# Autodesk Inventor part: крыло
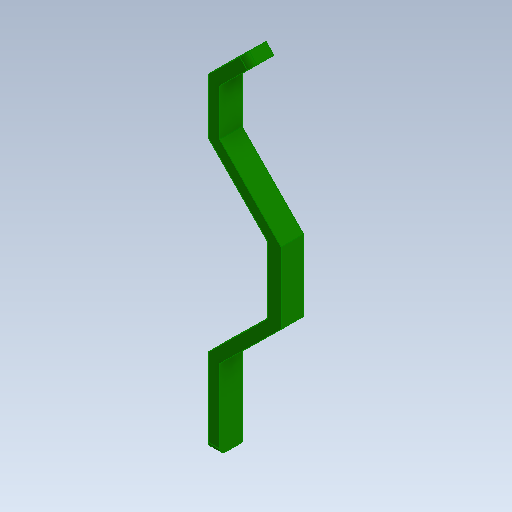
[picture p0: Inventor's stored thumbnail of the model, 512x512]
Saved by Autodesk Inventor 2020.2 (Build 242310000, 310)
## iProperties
Created: 2020-04
Part Number: крыло
Material: Типовые
Document SubType Name: Modeling
Designer: Алексей
Density: 1 g/cm^3
Appearance: По умолчанию
Author: Алексей
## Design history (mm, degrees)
sketch "Эскиз1"
  geometry: L1 (11, -78)-(4.414, -78) reference; L2 (11, -78)-(11, -74) reference; L3 (11, -74)-(25, -74) reference; L4 (25, -74)-(25, -78) reference; L5 (35, -78)-(25, -78) reference; L6 (35, -58)-(35, -78) reference; L7 (28.375, -58)-(35, -58) reference; L8 (35, -18)-(28.375, -18) reference; L9 (35, -2)-(35, -18) reference; L10 (35, -2)-(31, -2) reference; L11 (31, -2)-(31, 12) reference; L12 (31, 12)-(35, 12) reference; L13 (35, 28)-(35, 12) reference; L14 (28.375, 28)-(35, 28) reference; L15 (35, 68)-(28.375, 68) reference; L16 (35, 78)-(35, 68) reference; L17 (22, 78)-(35, 78) reference; L18 (22, 78)-(22, 74) reference; L19 (22, 74)-(8, 74) reference; L20 (8, 74)-(8, 78) reference; L21 (-5, 78)-(8, 78) reference; L22 (-7.718, 70.105)-(-5, 78) reference; L23 (-12.5, 67)-(-7.718, 70.105) reference; L24 (-13.093, 60.719)-(-12.5, 67) reference; L25 (-13.093, 60.719)-(-9.11, 60.343) reference; L26 (-9.11, 60.343)-(-10.425, 46.405) reference; L27 (-10.425, 46.405)-(-14.407, 46.781) reference; L28 (-15, 40.5)-(-14.407, 46.781) reference; L29 (-4.88, 34.8)-(-15, 40.5) reference; L30 (-2.58, 25.5)-(-4.88, 34.8) reference; L31 (-15.736, -18.735)-(-8.938, -18.9) reference; L32 (-34.328, -10.306)-(-15.736, -18.735) reference; L33 (-35, -16.306)-(-34.328, -10.306) reference; L34 (-26.476, -21.507)-(-35, -16.306) reference; L35 (-26.476, -21.507)-(-24.392, -18.092) reference; L36 (-24.392, -18.092)-(-12.441, -25.384) reference; L37 (-12.441, -25.384)-(-14.524, -28.799) reference; L38 (-6, -34)-(-14.524, -28.799) reference; L39 (-3.6, -49.087)-(-6, -34) reference; L40 (-3.6, -49.087)-(0.351, -48.458) reference; L41 (0.351, -48.458)-(2.55, -62.285) reference; L42 (2.55, -62.285)-(-1.4, -62.913) reference; L43 (0.464, -74.628)-(-1.4, -62.913) reference; L44 (8.375, -58)-(8.375, -29.617); L45 (8.375, -29.617)-(30.337, -8.02); L46 (30.337, -8.02)-(30.337, 17.48); L47 (30.337, 17.48)-(8.375, 39.814); L48 (8.375, 39.814)-(8.375, 56.383); L49 (8.375, 56.383)-(19.747, 67.565); L50 (19.747, 67.565)-(16.942, 70.417); L51 (16.942, 70.417)-(4.375, 58.059); L52 (4.375, 58.059)-(4.375, 38.177); L53 (4.375, 38.177)-(25.343, 16.854); L54 (25.343, 16.854)-(25.343, -7.321); L55 (25.343, -7.321)-(4.375, -27.941); L56 (4.375, -27.941)-(4.375, -58); L57 (4.375, -58)-(8.375, -58); L58 (-2.58, 25.5)-(15.848, 15.1) reference; L59 (15.848, 15.1)-(20.343, 10.529) reference; L60 (20.343, 10.529)-(20.343, -5.226) reference; L61 (20.343, -5.226)-(6.438, -18.9) reference; L62 (6.438, -18.9)-(-8.938, -18.9) reference; A1 r 4 centre (4.414, -74) between (0.464, -74.628) and (4.414, -78) reference; A2 r 20 centre (28.375, -38) between (28.375, -18) and (28.375, -58) reference; A3 r 20 centre (28.375, 48) between (28.375, 68) and (28.375, 28) reference; 1 further point
  constraints: 28 end point, 7 perpendicular, 5 tangent, 4 parallel, 2 point on line, 1 collinear, 1 vertical
  dimensions: "d0" = 4 distance between parallel lines of L56 L44; "d1" = 4 distance between parallel lines of L55 L45; "d2" = 4 distance between parallel lines of L53 L47; "d3" = 4 distance between parallel lines of L52 L48; "d4" = 4 distance between parallel lines of L51 L49
extrude "Выдавливание1" new body sketch "Эскиз1" distance "d5" = 8; taper "d6" = 0 deg
fillet "Сопряжение1" dims "d7" = 2
node "Твердое тело1"
node "Ссылка1"
